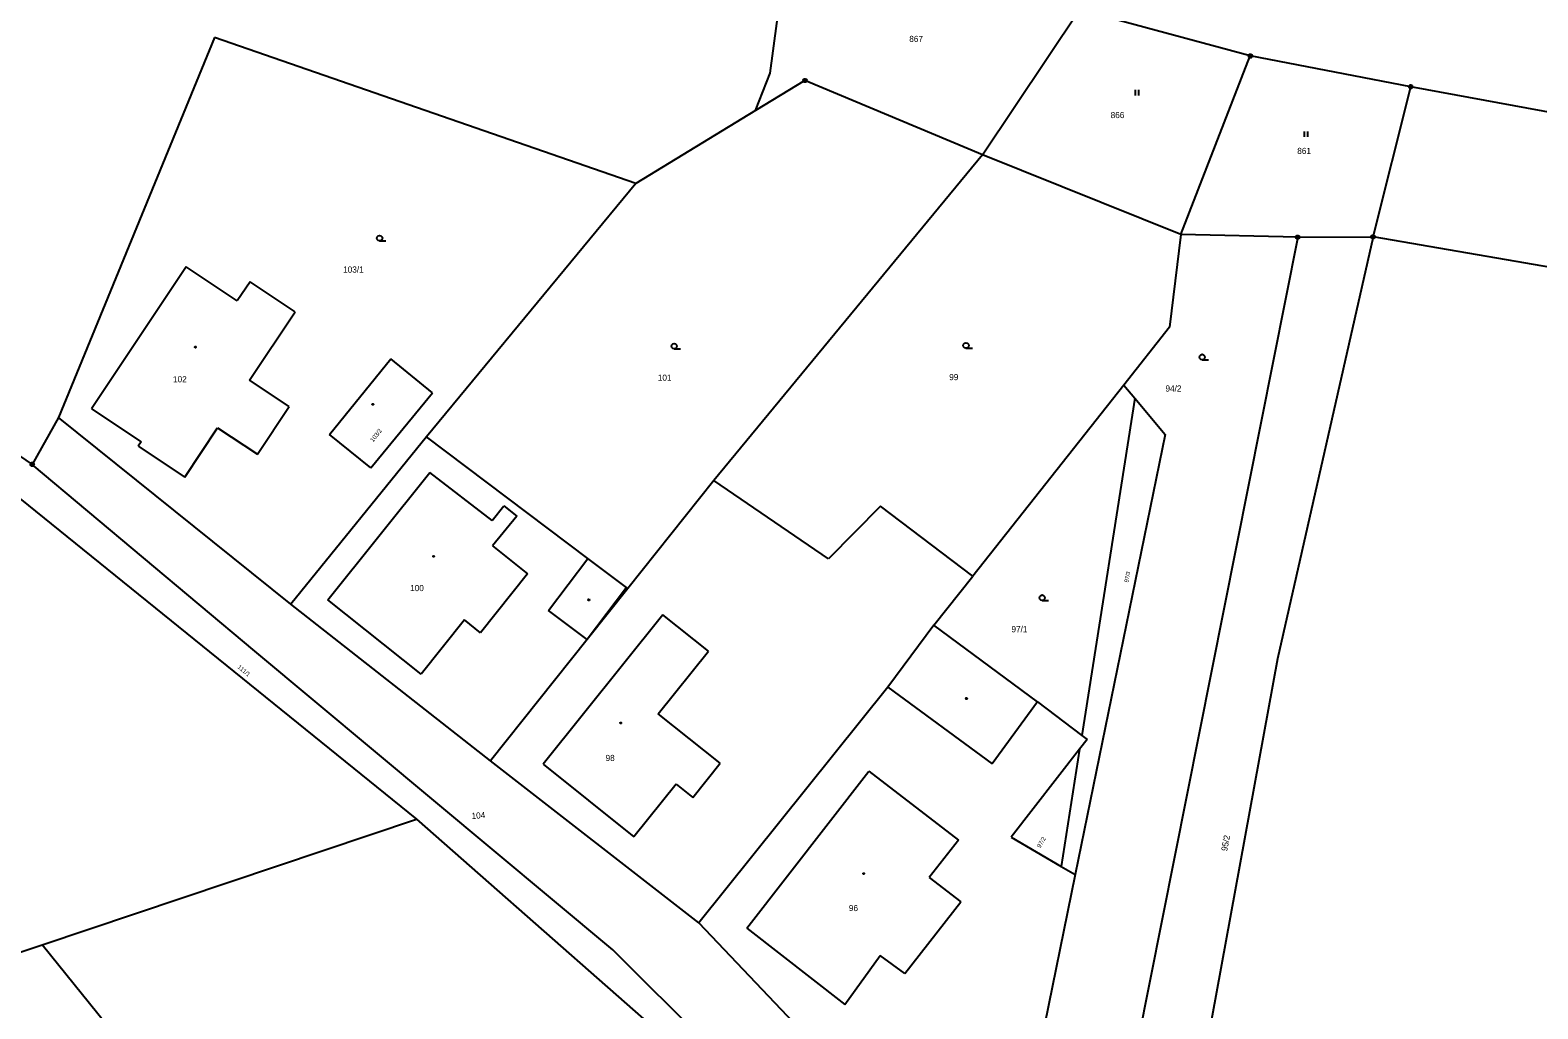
# Model space of a CAD drawing. Extents: x -871430 to -870620, y -1010094 to -1009649.
# Drawn here: x -870996.8 to -870892.6, y -1009799.4 to -1009731.8 of the extents above; entities that cross this region are included whole.
import ezdxf

# ---------------------------------------------------------------- set-up
doc = ezdxf.new("R2010")
doc.units = 0
for name, color, linetype in [('Vrstva 1', 7, 'Continuous'), ('Vrstva 2', 7, 'Continuous'), ('Vrstva 3', 7, 'Continuous'), ('Vrstva 4', 7, 'Continuous'), ('Vrstva 5', 7, 'Continuous'), ('Vrstva 8', 7, 'Continuous')]:
    doc.layers.add(name, color=color, linetype=linetype)

msp = doc.modelspace()

# ---------------------------------------------------------------- linework, layer by layer
at = {"layer": 'Vrstva 1'}
for p, q in [((-870945.62, -1009734.74), (-870944.1, -1009723.06)), ((-870930.97, -1009740.38), (-870924.25, -1009730.36)), ((-870912.46, -1009733.55), (-870924.25, -1009730.36)), ((-870984.02, -1009732.27), (-870994.79, -1009758.53)), ((-870954.91, -1009742.35), (-870984.02, -1009732.27)), ((-870917.26, -1009745.88), (-870912.46, -1009733.55)), ((-870901.37, -1009735.67), (-870912.46, -1009733.55)), ((-870946.64, -1009737.32), (-870945.62, -1009734.74)), ((-870943.23, -1009735.24), (-870946.64, -1009737.32)), ((-870930.97, -1009740.38), (-870943.23, -1009735.24)), ((-870903.98, -1009746.05), (-870901.37, -1009735.67)), ((-870860.24, -1009743.29), (-870901.37, -1009735.67)), ((-870946.64, -1009737.32), (-870954.91, -1009742.35)), ((-870930.97, -1009740.38), (-870949.52, -1009762.88)), ((-870917.26, -1009745.88), (-870930.97, -1009740.38)), ((-870954.91, -1009742.35), (-870969.36, -1009759.86)), ((-870909.18, -1009746.07), (-870922.93, -1009815.19)), ((-870917.26, -1009745.88), (-870918.03, -1009752.3)), ((-870909.18, -1009746.07), (-870917.26, -1009745.88)), ((-870903.98, -1009746.05), (-870910.58, -1009775.2)), ((-870909.18, -1009746.07), (-870903.98, -1009746.05)), ((-870852.35, -1009754.93), (-870903.98, -1009746.05)), ((-870985.98, -1009748.12), (-870992.52, -1009757.93)), ((-870982.44, -1009750.48), (-870985.98, -1009748.12)), ((-870981.55, -1009749.15), (-870982.44, -1009750.48)), ((-870978.45, -1009751.22), (-870981.55, -1009749.15)), ((-870981.61, -1009755.95), (-870978.45, -1009751.22)), ((-870918.03, -1009752.3), (-870921.19, -1009756.29)), ((-870976.07, -1009759.7), (-870971.84, -1009754.48)), ((-870968.95, -1009756.82), (-870971.84, -1009754.48)), ((-871006.12, -1009755.31), (-870996.61, -1009761.77)), ((-870978.86, -1009757.78), (-870981.61, -1009755.95)), ((-870973.21, -1009762.02), (-870968.95, -1009756.82)), ((-870921.19, -1009756.29), (-870931.62, -1009769.49)), ((-870920.44, -1009757.19), (-870924.1, -1009780.5)), ((-870921.19, -1009756.29), (-870920.44, -1009757.19)), ((-870920.44, -1009757.19), (-870918.35, -1009759.7)), ((-870992.52, -1009757.93), (-870989.09, -1009760.21)), ((-870981.05, -1009761.07), (-870978.86, -1009757.78)), ((-870994.79, -1009758.53), (-870996.61, -1009761.77)), ((-870978.75, -1009771.42), (-870994.79, -1009758.53)), ((-870986.07, -1009762.65), (-870983.8, -1009759.24)), ((-870983.8, -1009759.24), (-870981.05, -1009761.07)), ((-870989.09, -1009760.21), (-870989.28, -1009760.51)), ((-870969.36, -1009759.86), (-870978.75, -1009771.42)), ((-870973.21, -1009762.02), (-870976.07, -1009759.7)), ((-870958.22, -1009768.27), (-870969.36, -1009759.86)), ((-870918.35, -1009759.7), (-870924.55, -1009790.12)), ((-870989.28, -1009760.51), (-870986.07, -1009762.65)), ((-870981.23, -1009774.68), (-870996.61, -1009761.77)), ((-870949.52, -1009762.88), (-870955.46, -1009770.35)), ((-870941.59, -1009768.3), (-870949.52, -1009762.88)), ((-870997.47, -1009764.12), (-870970.06, -1009786.29)), ((-870938.01, -1009764.65), (-870941.59, -1009768.3)), ((-870931.62, -1009769.49), (-870938.01, -1009764.65)), ((-870955.55, -1009770.28), (-870958.22, -1009768.27)), ((-870934.33, -1009772.89), (-870931.62, -1009769.49)), ((-870955.46, -1009770.35), (-870958.27, -1009773.88)), ((-870955.46, -1009770.35), (-870955.55, -1009770.28)), ((-870964.94, -1009782.26), (-870978.75, -1009771.42)), ((-870934.33, -1009772.89), (-870937.49, -1009777.17)), ((-870927.15, -1009778.18), (-870934.33, -1009772.89)), ((-870958.27, -1009773.88), (-870964.94, -1009782.26)), ((-870956.49, -1009795.31), (-870981.23, -1009774.68)), ((-870910.58, -1009775.2), (-870917.75, -1009814.47)), ((-870937.49, -1009777.17), (-870950.56, -1009793.45)), ((-870927.15, -1009778.18), (-870924.1, -1009780.5)), ((-870923.73, -1009780.78), (-870924.25, -1009781.44)), ((-870924.1, -1009780.5), (-870923.73, -1009780.78)), ((-870950.56, -1009793.45), (-870964.94, -1009782.26)), ((-870924.25, -1009781.44), (-870928.98, -1009787.52)), ((-870924.25, -1009781.44), (-870925.52, -1009789.55)), ((-870995.93, -1009794.96), (-870970.06, -1009786.29)), ((-870970.06, -1009786.29), (-870944.09, -1009809.12)), ((-870928.98, -1009787.52), (-870925.52, -1009789.55)), ((-870925.52, -1009789.55), (-870924.55, -1009790.12)), ((-870924.55, -1009790.12), (-870929.69, -1009815.36)), ((-870929.69, -1009815.36), (-870950.56, -1009793.45)), ((-871005.04, -1009798.01), (-870995.93, -1009794.96)), ((-870977.29, -1009818.03), (-870995.93, -1009794.96)), ((-870938.72, -1009813.05), (-870956.49, -1009795.31))]:
    msp.add_line(p, q, dxfattribs=at)
at = {"layer": 'Vrstva 3'}
for p, q in [((-870920.415, -1009735.895), (-870920.415, -1009736.27)), ((-870920.165, -1009736.27), (-870920.165, -1009735.895)), ((-870908.745, -1009738.765), (-870908.745, -1009739.14)), ((-870908.495, -1009739.14), (-870908.495, -1009738.765))]:
    msp.add_line(p, q, dxfattribs=at)
for points in [[(-870972.61, -1009746.32), (-870972.705, -1009746.295), (-870972.772, -1009746.225), (-870972.798, -1009746.132), (-870972.772, -1009746.04), (-870972.705, -1009745.97), (-870972.61, -1009745.945), (-870972.515, -1009745.97), (-870972.448, -1009746.04), (-870972.422, -1009746.132), (-870972.448, -1009746.225), (-870972.515, -1009746.295), (-870972.61, -1009746.32), (-870972.172, -1009746.32)], [(-870952.26, -1009753.79), (-870952.355, -1009753.765), (-870952.422, -1009753.695), (-870952.448, -1009753.602), (-870952.422, -1009753.51), (-870952.355, -1009753.44), (-870952.26, -1009753.415), (-870952.165, -1009753.44), (-870952.098, -1009753.51), (-870952.072, -1009753.602), (-870952.098, -1009753.695), (-870952.165, -1009753.765), (-870952.26, -1009753.79), (-870951.822, -1009753.79)], [(-870932.1, -1009753.75), (-870932.195, -1009753.725), (-870932.262, -1009753.655), (-870932.288, -1009753.562), (-870932.262, -1009753.47), (-870932.195, -1009753.4), (-870932.1, -1009753.375), (-870932.005, -1009753.4), (-870931.938, -1009753.47), (-870931.912, -1009753.562), (-870931.938, -1009753.655), (-870932.005, -1009753.725), (-870932.1, -1009753.75), (-870931.662, -1009753.75)], [(-870915.79, -1009754.54), (-870915.885, -1009754.515), (-870915.952, -1009754.445), (-870915.978, -1009754.352), (-870915.952, -1009754.26), (-870915.885, -1009754.19), (-870915.79, -1009754.165), (-870915.695, -1009754.19), (-870915.628, -1009754.26), (-870915.602, -1009754.352), (-870915.628, -1009754.445), (-870915.695, -1009754.515), (-870915.79, -1009754.54), (-870915.352, -1009754.54)], [(-870926.84, -1009771.17), (-870926.935, -1009771.145), (-870927.002, -1009771.075), (-870927.028, -1009770.982), (-870927.002, -1009770.89), (-870926.935, -1009770.82), (-870926.84, -1009770.795), (-870926.745, -1009770.82), (-870926.678, -1009770.89), (-870926.652, -1009770.982), (-870926.678, -1009771.075), (-870926.745, -1009771.145), (-870926.84, -1009771.17), (-870926.402, -1009771.17)]]:
    msp.add_lwpolyline(points, dxfattribs=at)
at = {"layer": 'Vrstva 4'}
for p, q in [((-870976.19, -1009771.12), (-870969.15, -1009762.33)), ((-870964.84, -1009765.65), (-870969.15, -1009762.33)), ((-870964.84, -1009765.65), (-870964.02, -1009764.64)), ((-870963.14, -1009765.34), (-870964.8, -1009767.41)), ((-870964.02, -1009764.64), (-870963.14, -1009765.34)), ((-870964.8, -1009767.41), (-870962.4, -1009769.33)), ((-870960.94, -1009771.86), (-870958.22, -1009768.27)), ((-870962.4, -1009769.33), (-870965.65, -1009773.4)), ((-870955.55, -1009770.28), (-870958.27, -1009773.88)), ((-870969.75, -1009776.27), (-870976.19, -1009771.12)), ((-870958.27, -1009773.88), (-870960.94, -1009771.86)), ((-870966.75, -1009772.52), (-870969.75, -1009776.27)), ((-870965.65, -1009773.4), (-870966.75, -1009772.52)), ((-870953.05, -1009772.16), (-870961.31, -1009782.49)), ((-870949.9, -1009774.68), (-870953.05, -1009772.16)), ((-870953.36, -1009779), (-870949.9, -1009774.68)), ((-870937.49, -1009777.17), (-870930.3, -1009782.46)), ((-870949.08, -1009782.42), (-870953.36, -1009779)), ((-870927.15, -1009778.18), (-870930.3, -1009782.46)), ((-870961.31, -1009782.49), (-870955.04, -1009787.5)), ((-870950.97, -1009784.79), (-870949.08, -1009782.42)), ((-870947.25, -1009793.82), (-870938.81, -1009782.98)), ((-870938.81, -1009782.98), (-870932.62, -1009787.73)), ((-870952.13, -1009783.86), (-870955.04, -1009787.5)), ((-870952.13, -1009783.86), (-870950.97, -1009784.79)), ((-870932.62, -1009787.73), (-870934.64, -1009790.31)), ((-870934.64, -1009790.31), (-870932.46, -1009792.01)), ((-870936.32, -1009796.95), (-870932.46, -1009792.01)), ((-870947.25, -1009793.82), (-870940.48, -1009799.09)), ((-870940.48, -1009799.09), (-870938.04, -1009795.71)), ((-870936.32, -1009796.95), (-870938.04, -1009795.71))]:
    msp.add_line(p, q, dxfattribs=at)
at = {"layer": 'Vrstva 5'}
for points in [[(-870985.34, -1009753.628), (-870985.315, -1009753.633), (-870985.302, -1009753.655), (-870985.298, -1009753.67), (-870985.302, -1009753.692), (-870985.322, -1009753.71), (-870985.34, -1009753.712), (-870985.362, -1009753.705), (-870985.378, -1009753.69), (-870985.382, -1009753.67), (-870985.378, -1009753.648), (-870985.357, -1009753.63), (-870985.34, -1009753.628)], [(-870973.08, -1009757.578), (-870973.055, -1009757.582), (-870973.042, -1009757.605), (-870973.038, -1009757.62), (-870973.042, -1009757.642), (-870973.062, -1009757.66), (-870973.08, -1009757.662), (-870973.102, -1009757.655), (-870973.117, -1009757.64), (-870973.122, -1009757.62), (-870973.117, -1009757.598), (-870973.097, -1009757.58), (-870973.08, -1009757.578)], [(-870968.88, -1009768.078), (-870968.855, -1009768.082), (-870968.842, -1009768.105), (-870968.838, -1009768.12), (-870968.842, -1009768.142), (-870968.862, -1009768.16), (-870968.88, -1009768.162), (-870968.902, -1009768.155), (-870968.918, -1009768.14), (-870968.922, -1009768.12), (-870968.918, -1009768.098), (-870968.898, -1009768.08), (-870968.88, -1009768.078)], [(-870958.128, -1009771.092), (-870958.105, -1009771.13), (-870958.128, -1009771.168), (-870958.172, -1009771.168), (-870958.195, -1009771.13), (-870958.172, -1009771.092), (-870958.128, -1009771.092)], [(-870932.038, -1009777.912), (-870932.015, -1009777.95), (-870932.038, -1009777.987), (-870932.082, -1009777.987), (-870932.105, -1009777.95), (-870932.082, -1009777.912), (-870932.038, -1009777.912)], [(-870955.95, -1009779.598), (-870955.925, -1009779.602), (-870955.912, -1009779.625), (-870955.908, -1009779.64), (-870955.912, -1009779.662), (-870955.932, -1009779.68), (-870955.95, -1009779.682), (-870955.972, -1009779.675), (-870955.987, -1009779.66), (-870955.992, -1009779.64), (-870955.987, -1009779.618), (-870955.967, -1009779.6), (-870955.95, -1009779.598)], [(-870939.17, -1009790.008), (-870939.145, -1009790.013), (-870939.133, -1009790.035), (-870939.128, -1009790.05), (-870939.133, -1009790.072), (-870939.153, -1009790.09), (-870939.17, -1009790.092), (-870939.192, -1009790.085), (-870939.208, -1009790.07), (-870939.212, -1009790.05), (-870939.208, -1009790.028), (-870939.188, -1009790.01), (-870939.17, -1009790.008)]]:
    msp.add_lwpolyline(points, dxfattribs=at)
at = {"layer": 'Vrstva 8'}
for p, q in [((-870912.472, -1009733.55), (-870912.448, -1009733.55)), ((-870943.242, -1009735.24), (-870943.218, -1009735.24)), ((-870901.382, -1009735.67), (-870901.358, -1009735.67)), ((-870909.192, -1009746.07), (-870909.168, -1009746.07)), ((-870903.992, -1009746.05), (-870903.968, -1009746.05)), ((-870996.622, -1009761.77), (-870996.598, -1009761.77))]:
    msp.add_line(p, q, dxfattribs=at)
for points in [[(-870912.422, -1009733.43), (-870912.36, -1009733.478), (-870912.335, -1009733.55), (-870912.36, -1009733.622), (-870912.422, -1009733.67), (-870912.497, -1009733.67), (-870912.56, -1009733.622), (-870912.585, -1009733.55), (-870912.56, -1009733.478), (-870912.497, -1009733.43), (-870912.422, -1009733.43)], [(-870943.192, -1009735.12), (-870943.13, -1009735.168), (-870943.105, -1009735.24), (-870943.13, -1009735.312), (-870943.192, -1009735.36), (-870943.268, -1009735.36), (-870943.33, -1009735.312), (-870943.355, -1009735.24), (-870943.33, -1009735.168), (-870943.268, -1009735.12), (-870943.192, -1009735.12)], [(-870901.332, -1009735.55), (-870901.27, -1009735.598), (-870901.245, -1009735.67), (-870901.27, -1009735.742), (-870901.332, -1009735.79), (-870901.408, -1009735.79), (-870901.47, -1009735.742), (-870901.495, -1009735.67), (-870901.47, -1009735.598), (-870901.408, -1009735.55), (-870901.332, -1009735.55)], [(-870909.143, -1009745.95), (-870909.08, -1009745.997), (-870909.055, -1009746.07), (-870909.08, -1009746.142), (-870909.143, -1009746.19), (-870909.218, -1009746.19), (-870909.28, -1009746.142), (-870909.305, -1009746.07), (-870909.28, -1009745.997), (-870909.218, -1009745.95), (-870909.143, -1009745.95)], [(-870903.942, -1009745.93), (-870903.88, -1009745.978), (-870903.855, -1009746.05), (-870903.88, -1009746.122), (-870903.942, -1009746.17), (-870904.018, -1009746.17), (-870904.08, -1009746.122), (-870904.105, -1009746.05), (-870904.08, -1009745.978), (-870904.018, -1009745.93), (-870903.942, -1009745.93)], [(-870996.572, -1009761.65), (-870996.51, -1009761.698), (-870996.485, -1009761.77), (-870996.51, -1009761.842), (-870996.572, -1009761.89), (-870996.648, -1009761.89), (-870996.71, -1009761.842), (-870996.735, -1009761.77), (-870996.71, -1009761.698), (-870996.648, -1009761.65), (-870996.572, -1009761.65)]]:
    msp.add_lwpolyline(points, dxfattribs=at)

# ---------------------------------------------------------------- texts
at = {"layer": 'Vrstva 2'}
for s, p in [('867', (-870936.019, -1009732.582)), ('866', (-870922.107, -1009737.842)), ('861', (-870909.215, -1009740.322)), ('103/1', (-870975.132, -1009748.52)), ('102', (-870986.882, -1009756.1)), ('101', (-870953.392, -1009755.99)), ('99', (-870933.261, -1009755.95)), ('94/2', (-870918.321, -1009756.74)), ('100', (-870970.502, -1009770.53)), ('97/1', (-870928.961, -1009773.37)), ('98', (-870957.001, -1009782.27)), ('96', (-870940.191, -1009792.64))]:
    msp.add_text(s, height=0.425, dxfattribs=at).set_placement(p)
for s, height, rotation, p in [('103/2', 0.2975, 51.79538, (-870973.057, -1009760.256)), ('97/3', 0.285, 78.7817, (-870920.892, -1009769.951)), ('111/1', 0.285, 320.398, (-870982.449, -1009775.822)), ('104', 0.425, 4.64096, (-870966.242, -1009786.282)), ('95/2', 0.425, 79.24006, (-870914.059, -1009788.522)), ('97/2', 0.2975, 59.41572, (-870926.969, -1009788.304))]:
    msp.add_text(s, height=height, rotation=rotation, dxfattribs=at).set_placement(p)

doc.saveas('drawing.dxf')
